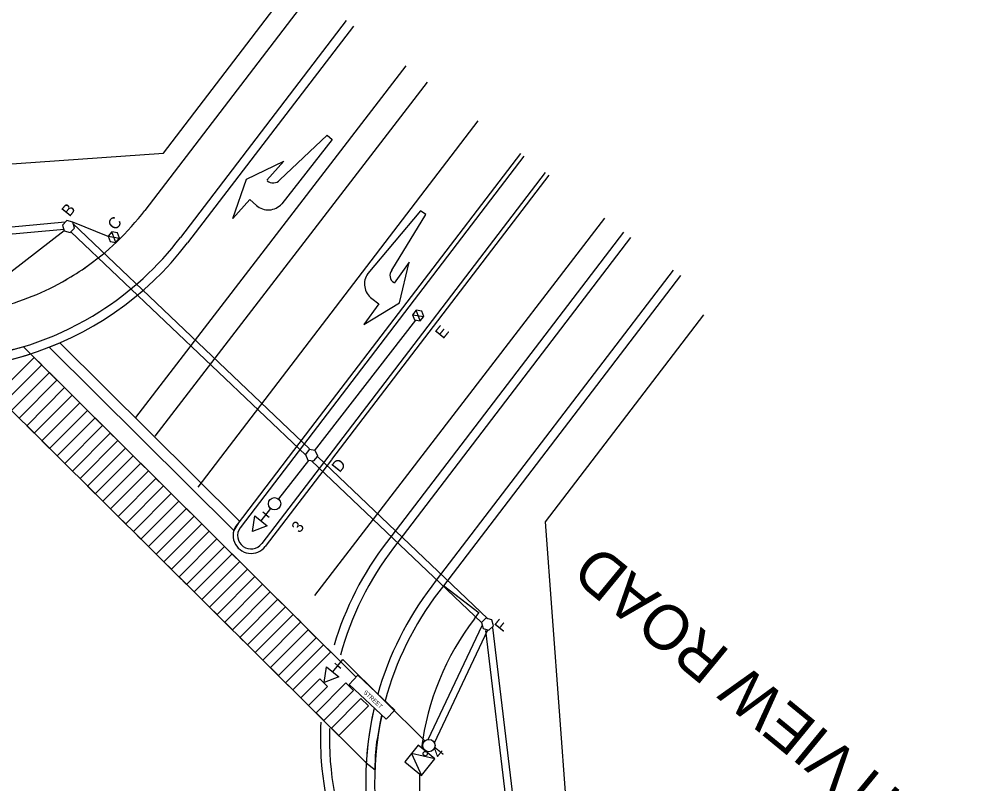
# Model space of a CAD drawing. Extents: x 592613 to 600223, y 4837996 to 4840103.
# Drawn here: x 593021.3 to 593074.7, y 4839326.1 to 4839368.8 of the extents above; entities that cross this region are included whole.
import ezdxf

# ---------------------------------------------------------------- set-up
doc = ezdxf.new("R2010")
doc.units = 0
for name, color, linetype in [('ENG_CURB-BACK', 7, 'Continuous'), ('ENG_EPAVT', 7, 'Continuous'), ('ENG_LANEWAY', 7, 'Continuous'), ('ENG_LIMITS', 7, 'Continuous'), ('ENG_SIDEWALK', 7, 'Continuous'), ('Level 12', 7, 'Continuous'), ('Level 32', 7, 'Continuous'), ('PMK_LANE', 7, 'Continuous'), ('ROW_ENG_ROW', 7, 'Continuous'), ('ROW_ENG_ROW BO', 7, 'Continuous'), ('TCS_100mm-NEW', 7, 'Continuous'), ('TCS_50mm-NEW', 7, 'Continuous'), ('TCS_75mm-NEW', 7, 'Continuous'), ('TCS_ELEC-CHAMBER-NEW', 7, 'Continuous'), ('TCS_LUMINAIRE-NEW', 7, 'Continuous'), ('TCS_POLE-NEW', 7, 'Continuous'), ('TCS_PUSHBUTTON', 7, 'Continuous'), ('TCS_SIGN', 7, 'Continuous'), ('TCS_SIGNALHEAD', 7, 'Continuous')]:
    doc.layers.add(name, color=color, linetype=linetype)

msp = doc.modelspace()

# ---------------------------------------------------------------- linework, layer by layer
at = {"layer": 'ENG_CURB-BACK'}
for p, q in [((593037.601, 4839370.274), (593028.34, 4839358.144)), ((593039.589, 4839368.757), (593030.327, 4839356.627)), ((593049.524, 4839361.172), (593037.741, 4839345.74)), ((593055.485, 4839356.62), (593042.238, 4839339.271)), ((593058.267, 4839354.496), (593045.02, 4839337.147)), ((593045.02, 4839337.147), (593044.766, 4839336.815))]:
    msp.add_line(p, q, dxfattribs=at)
for centre, start, end in [((593016.418, 4839367.247), 302.2959, 322.6377), ((593016.418, 4839367.247), 252.0777, 302.4982), ((593056.147, 4839328.651), 142.6377, 164.7037), ((593058.676, 4839326.195), 142.6377, 165.0787), ((593058.676, 4839326.195), 167.7306, 225.8289), ((593056.147, 4839328.651), 178.3407, 225.8289)]:
    msp.add_arc(centre, 17.5, start, end, dxfattribs=at)
at = {"layer": 'ENG_EPAVT'}
for p, q in [((593039.986, 4839368.454), (593030.724, 4839356.324)), ((593049.325, 4839361.324), (593037.593, 4839345.958)), ((593050.716, 4839360.262), (593038.612, 4839344.408)), ((593050.915, 4839360.11), (593038.769, 4839344.202)), ((593055.087, 4839356.924), (593041.841, 4839339.574)), ((593057.869, 4839354.8), (593044.623, 4839337.45)), ((593037.593, 4839345.958), (593033.488, 4839340.581)), ((593037.739, 4839345.737), (593033.656, 4839340.389)), ((593038.612, 4839344.408), (593034.865, 4839339.501)), ((593038.764, 4839344.196), (593035.064, 4839339.35)), ((593044.623, 4839337.45), (593044.369, 4839337.118))]:
    msp.add_line(p, q, dxfattribs=at)
for centre, radius, start, end in [((593016.418, 4839367.247), 18, 251.2988, 322.6377), ((593034.266, 4839339.953), 1, 141.1016, 322.9443), ((593034.266, 4839339.953), 0.75, 144.4115, 322.9443), ((593056.147, 4839328.651), 18, 142.6377, 163.3105), ((593058.676, 4839326.195), 18, 142.6377, 164.2273), ((593058.676, 4839326.195), 18, 166.783, 225.8289), ((593056.147, 4839328.651), 18, 177.2458, 184.2333), ((593056.147, 4839328.651), 18, 184.2333, 225.8289)]:
    msp.add_arc(centre, radius, start, end, dxfattribs=at)
at = {"layer": 'ENG_LANEWAY'}
for p, q in [((593042.918, 4839366.236), (593027.804, 4839346.549)), ((593044.108, 4839365.323), (593028.894, 4839345.505)), ((593054.023, 4839357.711), (593037.814, 4839336.598))]:
    msp.add_line(p, q, dxfattribs=at)
at = {"layer": 'ENG_LIMITS'}
for points in [[(593021.943, 4839350.116), (593021.547, 4839350.517), (593021.305, 4839350.439), (593020.844, 4839350.315), (593019.495, 4839350.021), (593017.993, 4839349.811), (593016.907, 4839349.761), (593016.364, 4839349.736), (593015.377, 4839349.781), (593015.176, 4839349.29), (593015.718, 4839349.259), (593016.239, 4839349.25), (593016.733, 4839349.253), (593016.997, 4839349.255), (593017.455, 4839349.278), (593018.049, 4839349.323), (593018.648, 4839349.386), (593019.737, 4839349.555), (593016.278, 4839349.248), (593019.722, 4839349.553), (593019.968, 4839349.607), (593020.78, 4839349.784), (593021.472, 4839349.975)], [(593040.707, 4839327.25), (593041.205, 4839326.846), (593041.221, 4839327.639), (593041.303, 4839328.414), (593041.351, 4839328.666), (593041.479, 4839329.443), (593041.575, 4839329.914), (593041.152, 4839330.31), (593040.978, 4839329.511), (593040.87, 4839328.823), (593040.816, 4839328.432), (593040.775, 4839328.068)]]:
    msp.add_lwpolyline(points, close=True, dxfattribs=at)
at = {"layer": 'ENG_SIDEWALK'}
for p, q in [((593047.019, 4839335.62), (593045.02, 4839337.147)), ((593046.61, 4839335.933), (593045.02, 4839337.147)), ((593046.753, 4839335.297), (593047.007, 4839335.63))]:
    msp.add_line(p, q, dxfattribs=at)
for centre, start, end in [((593016.418, 4839367.247), 304.5902, 322.6377), ((593016.418, 4839367.247), 299.7989, 305.4959), ((593016.418, 4839367.247), 283.8878, 300.1512), ((593058.676, 4839326.195), 142.6377, 172.7872), ((593058.676, 4839326.195), 178.3521, 199.4407)]:
    msp.add_arc(centre, 15, start, end, dxfattribs=at)
at = {"layer": 'Level 12'}
for p, q in [((593035.881, 4839359.844), (593038.529, 4839362.358)), ((593038.802, 4839362.115), (593035.98, 4839358.504)), ((593038.529, 4839362.358), (593038.802, 4839362.115)), ((593034.007, 4839359.886), (593036.109, 4839360.894)), ((593036.109, 4839360.894), (593035.154, 4839359.823)), ((593033.243, 4839357.683), (593034.007, 4839359.886)), ((593034.199, 4839358.754), (593033.243, 4839357.683)), ((593034.568, 4839358.424), (593034.199, 4839358.754)), ((593043.737, 4839358.126), (593040.799, 4839354.609)), ((593042.13, 4839354.794), (593044.033, 4839357.91)), ((593044.033, 4839357.91), (593043.737, 4839358.126)), ((593043.109, 4839355.237), (593042.263, 4839354.078)), ((593042.565, 4839352.97), (593043.109, 4839355.237)), ((593040.572, 4839351.761), (593042.565, 4839352.97)), ((593041.418, 4839352.92), (593040.572, 4839351.761)), ((593041.018, 4839353.212), (593041.418, 4839352.92))]:
    msp.add_line(p, q, dxfattribs=at)
for centre, radius, start, end in [((593035.509, 4839360.177), 0.5, 228.2469, 318.2706), ((593035.234, 4839359.17), 1, 228.242, 318.2642), ((593041.607, 4839354.02), 1, 143.8506, 233.8728), ((593042.534, 4839354.499), 0.5, 143.8443, 233.8679)]:
    msp.add_arc(centre, radius, start, end, dxfattribs=at)
at = {"layer": 'PMK_LANE'}
for p, q in [((593046.941, 4839363.144), (593031.299, 4839342.658)), ((593023.588, 4839350.737), (593033.628, 4839340.765)), ((593022.987, 4839350.489), (593033.307, 4839340.238)), ((593022.143, 4839349.918), (593020.026, 4839347.792)), ((593021.943, 4839350.116), (593037.307, 4839334.856)), ((593022.568, 4839349.495), (593022.143, 4839349.918)), ((593020.452, 4839347.369), (593022.568, 4839349.495)), ((593022.994, 4839349.072), (593020.878, 4839346.946)), ((593023.42, 4839348.649), (593022.994, 4839349.072)), ((593018.963, 4839348.848), (593040.707, 4839327.25)), ((593021.303, 4839346.523), (593023.42, 4839348.649)), ((593023.845, 4839348.227), (593021.729, 4839346.1)), ((593024.271, 4839347.804), (593023.845, 4839348.227)), ((593022.155, 4839345.678), (593024.271, 4839347.804)), ((593020.878, 4839346.946), (593021.303, 4839346.523)), ((593024.697, 4839347.381), (593022.58, 4839345.255)), ((593023.006, 4839344.832), (593025.123, 4839346.958)), ((593025.123, 4839346.958), (593024.697, 4839347.381)), ((593025.548, 4839346.535), (593023.432, 4839344.409)), ((593025.974, 4839346.112), (593025.548, 4839346.535)), ((593021.729, 4839346.1), (593022.155, 4839345.678)), ((593023.858, 4839343.986), (593025.974, 4839346.112)), ((593026.4, 4839345.69), (593024.283, 4839343.563)), ((593026.825, 4839345.267), (593026.4, 4839345.69)), ((593022.58, 4839345.255), (593023.006, 4839344.832)), ((593024.709, 4839343.141), (593026.825, 4839345.267)), ((593027.251, 4839344.844), (593025.135, 4839342.718)), ((593027.677, 4839344.421), (593027.251, 4839344.844)), ((593023.432, 4839344.409), (593023.858, 4839343.986)), ((593025.56, 4839342.295), (593027.677, 4839344.421)), ((593028.102, 4839343.998), (593025.986, 4839341.872)), ((593028.528, 4839343.575), (593028.102, 4839343.998)), ((593024.283, 4839343.563), (593024.709, 4839343.141)), ((593026.412, 4839341.449), (593028.528, 4839343.575)), ((593025.135, 4839342.718), (593025.56, 4839342.295)), ((593028.954, 4839343.153), (593026.837, 4839341.026)), ((593027.263, 4839340.604), (593029.38, 4839342.73)), ((593029.38, 4839342.73), (593028.954, 4839343.153)), ((593029.805, 4839342.307), (593027.689, 4839340.181)), ((593030.231, 4839341.884), (593029.805, 4839342.307)), ((593025.986, 4839341.872), (593026.412, 4839341.449)), ((593028.114, 4839339.758), (593030.231, 4839341.884)), ((593030.657, 4839341.461), (593028.54, 4839339.335)), ((593031.082, 4839341.038), (593030.657, 4839341.461)), ((593026.837, 4839341.026), (593027.263, 4839340.604)), ((593028.966, 4839338.912), (593031.082, 4839341.038)), ((593031.508, 4839340.616), (593029.392, 4839338.489)), ((593031.934, 4839340.193), (593031.508, 4839340.616)), ((593027.689, 4839340.181), (593028.114, 4839339.758)), ((593029.817, 4839338.067), (593031.934, 4839340.193)), ((593032.359, 4839339.77), (593030.243, 4839337.644)), ((593032.785, 4839339.347), (593032.359, 4839339.77)), ((593028.54, 4839339.335), (593028.966, 4839338.912)), ((593030.669, 4839337.221), (593032.785, 4839339.347)), ((593033.211, 4839338.924), (593031.094, 4839336.798)), ((593033.636, 4839338.501), (593033.211, 4839338.924)), ((593029.392, 4839338.489), (593029.817, 4839338.067)), ((593031.52, 4839336.375), (593033.636, 4839338.501)), ((593034.062, 4839338.079), (593031.946, 4839335.952)), ((593034.488, 4839337.656), (593034.062, 4839338.079)), ((593030.243, 4839337.644), (593030.669, 4839337.221)), ((593032.371, 4839335.53), (593034.488, 4839337.656)), ((593031.094, 4839336.798), (593031.52, 4839336.375)), ((593034.914, 4839337.233), (593032.797, 4839335.107)), ((593033.223, 4839334.684), (593035.339, 4839336.81)), ((593035.339, 4839336.81), (593034.914, 4839337.233)), ((593035.765, 4839336.387), (593033.649, 4839334.261)), ((593036.191, 4839335.965), (593035.765, 4839336.387)), ((593031.946, 4839335.952), (593032.371, 4839335.53)), ((593034.074, 4839333.838), (593036.191, 4839335.965)), ((593036.616, 4839335.542), (593034.5, 4839333.415)), ((593037.042, 4839335.119), (593036.616, 4839335.542)), ((593032.797, 4839335.107), (593033.223, 4839334.684)), ((593034.926, 4839332.993), (593037.042, 4839335.119)), ((593037.457, 4839334.686), (593035.351, 4839332.57)), ((593037.307, 4839334.856), (593040.144, 4839332.038)), ((593037.913, 4839334.234), (593037.457, 4839334.686)), ((593033.649, 4839334.261), (593034.074, 4839333.838)), ((593035.806, 4839332.118), (593037.913, 4839334.234)), ((593038.319, 4839333.85), (593036.203, 4839331.724)), ((593038.725, 4839333.447), (593038.319, 4839333.85)), ((593034.5, 4839333.415), (593034.926, 4839332.993)), ((593036.609, 4839331.321), (593038.725, 4839333.447)), ((593035.351, 4839332.57), (593035.806, 4839332.118)), ((593036.203, 4839331.724), (593036.609, 4839331.321)), ((593038.112, 4839331.942), (593037.054, 4839330.878)), ((593037.48, 4839330.456), (593038.538, 4839331.519)), ((593039.572, 4839331.707), (593037.905, 4839330.033)), ((593038.538, 4839331.519), (593038.112, 4839331.942)), ((593039.998, 4839331.283), (593039.572, 4839331.707)), ((593038.332, 4839329.609), (593039.998, 4839331.283)), ((593037.054, 4839330.878), (593037.48, 4839330.456)), ((593040.41, 4839330.848), (593038.757, 4839329.187)), ((593039.183, 4839328.764), (593040.836, 4839330.424)), ((593040.836, 4839330.424), (593040.41, 4839330.848)), ((593037.905, 4839330.033), (593038.332, 4839329.609)), ((593038.757, 4839329.187), (593039.183, 4839328.764))]:
    msp.add_line(p, q, dxfattribs=at)
msp.add_lwpolyline([(593022.987, 4839350.489), (593023.588, 4839350.737), (593033.628, 4839340.765), (593033.307, 4839340.238)], close=True, dxfattribs=at)
at = {"layer": 'ROW_ENG_ROW'}
for p, q in [((593009.576, 4839359.952), (593029.37, 4839361.343)), ((593052.389, 4839318.36), (593050.733, 4839340.727))]:
    msp.add_line(p, q, dxfattribs=at)
at = {"layer": 'ROW_ENG_ROW BO'}
for p, q in [((593029.37, 4839361.343), (593038.41, 4839373.182)), ((593050.733, 4839340.727), (593059.567, 4839352.296))]:
    msp.add_line(p, q, dxfattribs=at)
at = {"layer": 'TCS_100mm-NEW'}
for p, q in [((593023.873, 4839357.487), (593012.289, 4839356.403)), ((593037.532, 4839344.796), (593024.307, 4839357.401)), ((593047.494, 4839335.303), (593037.978, 4839344.371)), ((593037.483, 4839344.151), (593035.798, 4839342.005)), ((593044.177, 4839328.551), (593047.188, 4839334.921)), ((593049.863, 4839317.287), (593047.783, 4839334.814))]:
    msp.add_line(p, q, dxfattribs=at)
at = {"layer": 'TCS_50mm-NEW'}
for p, q in [((593023.817, 4839357.08), (593012.71, 4839356.041)), ((593026.289, 4839356.679), (593024.307, 4839357.479)), ((593037.323, 4839344.445), (593024.2, 4839356.95)), ((593037.818, 4839344.698), (593043.481, 4839351.996)), ((593047.143, 4839335.088), (593037.649, 4839344.134)), ((593044.525, 4839328.351), (593047.494, 4839334.68)), ((593049.413, 4839317.684), (593047.4, 4839334.652))]:
    msp.add_line(p, q, dxfattribs=at)
at = {"layer": 'TCS_75mm-NEW'}
msp.add_line((593023.818, 4839356.99), (593019.379, 4839353.554), dxfattribs=at)
at = {"layer": 'TCS_ELEC-CHAMBER-NEW'}
for p, q in [((593023.973, 4839357.568), (593023.729, 4839357.324)), ((593023.729, 4839357.324), (593023.818, 4839356.99)), ((593024.307, 4839357.479), (593023.973, 4839357.568)), ((593024.152, 4839356.9), (593024.397, 4839357.145)), ((593024.397, 4839357.145), (593024.307, 4839357.479)), ((593023.818, 4839356.99), (593024.152, 4839356.9)), ((593026.483, 4839356.944), (593026.282, 4839356.696)), ((593026.282, 4839356.696), (593026.912, 4839356.597)), ((593026.282, 4839356.696), (593026.397, 4839356.399)), ((593026.712, 4839356.349), (593026.483, 4839356.944)), ((593026.798, 4839356.895), (593026.483, 4839356.944)), ((593026.712, 4839356.349), (593026.912, 4839356.597)), ((593026.912, 4839356.597), (593026.798, 4839356.895)), ((593026.397, 4839356.399), (593026.712, 4839356.349)), ((593043.498, 4839352.557), (593043.297, 4839352.309)), ((593043.297, 4839352.309), (593043.927, 4839352.21)), ((593043.297, 4839352.309), (593043.412, 4839352.011)), ((593043.727, 4839351.962), (593043.498, 4839352.557)), ((593043.813, 4839352.507), (593043.498, 4839352.557)), ((593043.927, 4839352.21), (593043.813, 4839352.507)), ((593043.412, 4839352.011), (593043.727, 4839351.962)), ((593043.727, 4839351.962), (593043.927, 4839352.21)), ((593037.517, 4839344.765), (593037.307, 4839344.491)), ((593037.307, 4839344.491), (593037.438, 4839344.172)), ((593037.86, 4839344.72), (593037.517, 4839344.765)), ((593037.781, 4839344.126), (593037.992, 4839344.4)), ((593037.992, 4839344.4), (593037.86, 4839344.72)), ((593037.438, 4839344.172), (593037.781, 4839344.126)), ((593047.388, 4839335.332), (593047.143, 4839335.088)), ((593047.721, 4839335.243), (593047.388, 4839335.332)), ((593047.811, 4839334.909), (593047.721, 4839335.243)), ((593047.143, 4839335.088), (593047.233, 4839334.754)), ((593047.233, 4839334.754), (593047.567, 4839334.664)), ((593047.567, 4839334.664), (593047.811, 4839334.909))]:
    msp.add_line(p, q, dxfattribs=at)
at = {"layer": 'TCS_LUMINAIRE-NEW'}
msp.add_line((593039.392, 4839333.014), (593043.982, 4839328.466), dxfattribs=at)
at = {"layer": 'TCS_POLE-NEW'}
for centre in [(593035.584, 4839341.734), (593044.211, 4839328.207)]:
    msp.add_circle(centre, 0.346, dxfattribs=at)
at = {"layer": 'TCS_PUSHBUTTON'}
msp.add_circle((593044.002, 4839327.756), 0.12, dxfattribs=at)
at = {"layer": 'TCS_SIGN'}
msp.add_lwpolyline([(593040.235, 4839332.136), (593042.311, 4839330.19), (593041.829, 4839329.676), (593039.754, 4839331.622)], close=True, dxfattribs=at)
at = {"layer": 'TCS_SIGNALHEAD'}
for p, q in [((593034.825, 4839340.774), (593035.382, 4839341.459)), ((593035.104, 4839341.116), (593034.933, 4839341.256)), ((593035.104, 4839341.116), (593035.275, 4839340.977)), ((593034.343, 4839340.181), (593034.483, 4839341.053)), ((593034.483, 4839341.053), (593035.167, 4839340.496)), ((593035.167, 4839340.496), (593034.343, 4839340.181)), ((593038.353, 4839331.735), (593038.493, 4839332.607)), ((593038.493, 4839332.607), (593039.177, 4839332.05)), ((593038.835, 4839332.328), (593039.392, 4839333.014)), ((593039.114, 4839332.671), (593038.943, 4839332.81)), ((593039.114, 4839332.671), (593039.285, 4839332.532)), ((593039.177, 4839332.05), (593038.353, 4839331.735)), ((593043.61, 4839328.227), (593042.856, 4839327.293)), ((593044.544, 4839327.472), (593043.61, 4839328.227)), ((593042.856, 4839327.293), (593043.789, 4839326.539))]:
    msp.add_line(p, q, dxfattribs=at)
for points in [[(593034.483, 4839341.053), (593035.167, 4839340.496), (593034.343, 4839340.181), (593034.343, 4839340.181)], [(593038.493, 4839332.607), (593039.177, 4839332.05), (593038.353, 4839331.735), (593038.353, 4839331.735)], [(593043.789, 4839326.539), (593044.544, 4839327.472), (593043.233, 4839327.76), (593043.233, 4839327.76)]]:
    msp.add_lwpolyline(points, close=True, dxfattribs=at)

# ---------------------------------------------------------------- texts
at = {"layer": 'Level 32'}
msp.add_text('CREDITVIEW ROAD', height=2.5, rotation=140.5921, dxfattribs=at).set_placement((593078.063, 4839319.521))
at = {"layer": 'TCS_ELEC-CHAMBER-NEW'}
for s, p in [('B', (593024.123, 4839357.747)), ('C', (593026.693, 4839356.984)), ('E', (593045.005, 4839350.914)), ('D', (593039.22, 4839343.439)), ('F', (593048.324, 4839334.512))]:
    msp.add_text(s, height=0.65, rotation=51.0574, dxfattribs=at).set_placement(p)
at = {"layer": 'TCS_POLE-NEW'}
for s, p in [('3', (593036.976, 4839340.058)), ('4', (593044.805, 4839327.452))]:
    msp.add_text(s, height=0.65, rotation=51.0574, dxfattribs=at).set_placement(p)
at = {"layer": 'TCS_SIGN'}
msp.add_text('STREET', height=0.2407, rotation=316.8381, dxfattribs=at).set_placement((593040.533, 4839331.153))

doc.saveas('drawing.dxf')
